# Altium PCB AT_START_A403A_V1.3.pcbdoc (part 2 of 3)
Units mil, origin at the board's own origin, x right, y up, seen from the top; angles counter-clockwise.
Board outline 6370 x 3956 mil, 2 copper layers (Top Layer, Bottom Layer); 182 components, 198 nets, 768 pads, 894 vias.
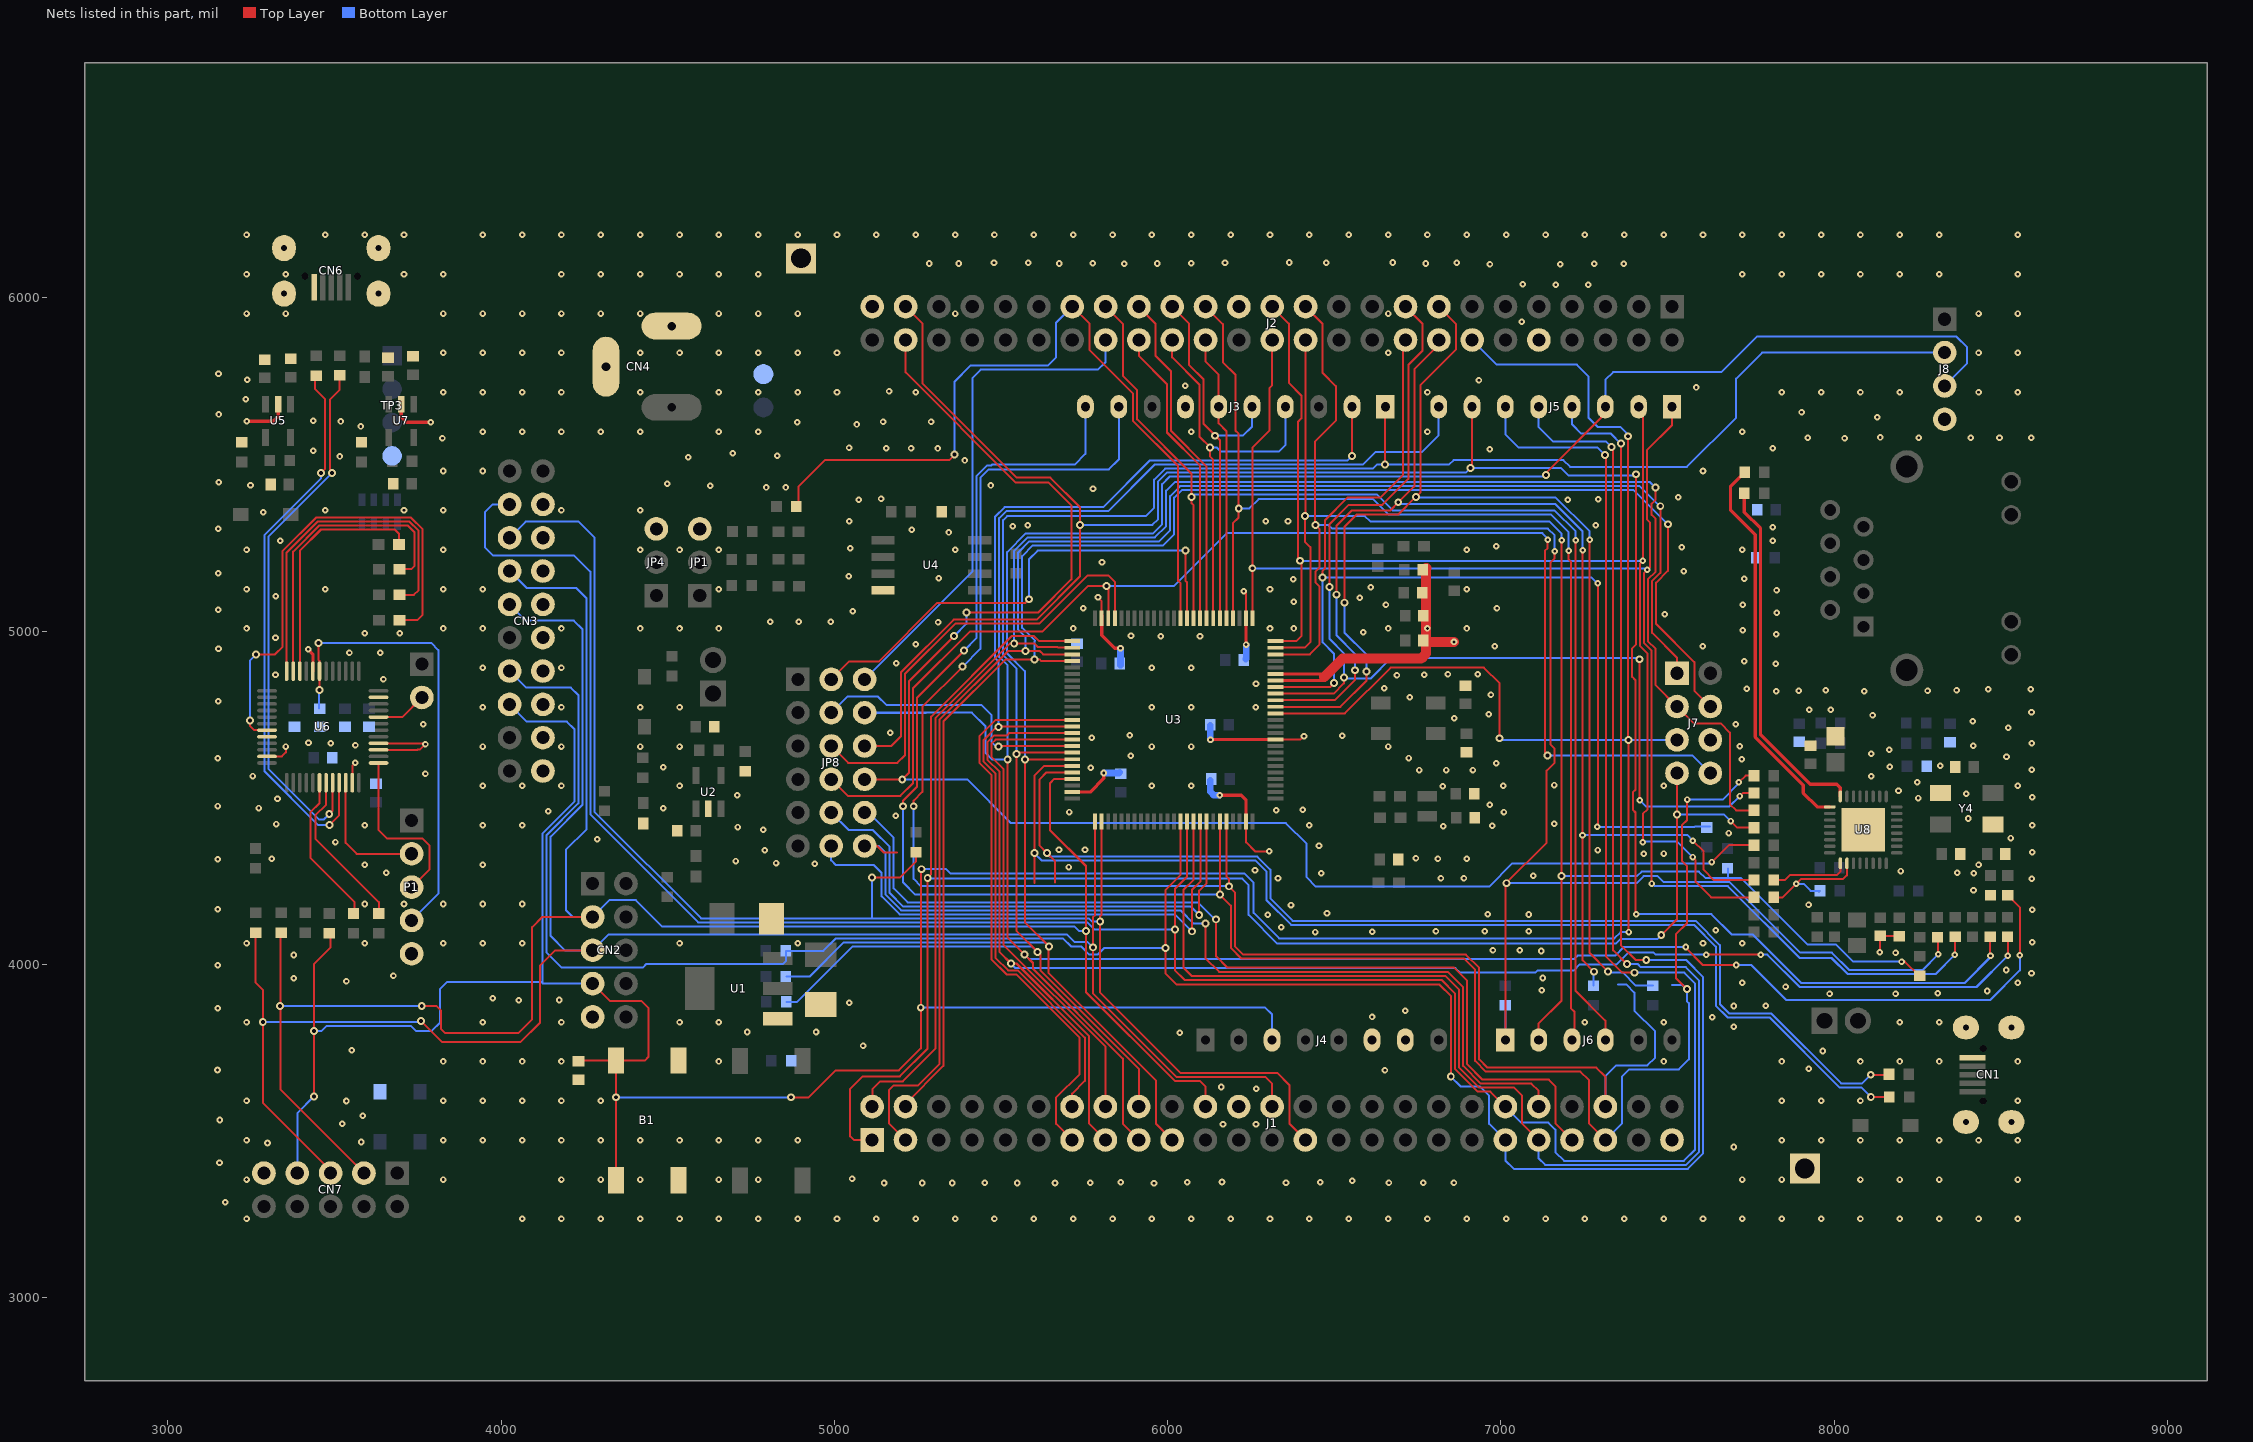
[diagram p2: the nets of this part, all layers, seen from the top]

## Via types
v1: diameter 19.68, hole 7.87, Top Layer to Bottom Layer, 702 vias
v2: diameter 23.62, hole 11.81, Top Layer to Bottom Layer, 166 vias
v3: diameter 35.43, hole 19.68, Top Layer to Bottom Layer, 10 vias
v4: diameter 25.98, hole 12.99, Top Layer to Bottom Layer, 9 vias
v5: diameter 27.56, hole 15.75, Top Layer to Bottom Layer, 5 vias
v6: diameter 43.31, hole 21.65, Top Layer to Bottom Layer, 1 vias
v7: diameter 31.5, hole 19.68, Top Layer to Bottom Layer, 1 vias

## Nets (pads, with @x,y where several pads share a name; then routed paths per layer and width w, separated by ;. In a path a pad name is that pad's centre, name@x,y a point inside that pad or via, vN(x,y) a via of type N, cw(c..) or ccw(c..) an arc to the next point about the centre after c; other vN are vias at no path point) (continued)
GND: B1.2 C1.1 C2.1 C3.1 C4.1 C5.2 C6.2 C7.2 C8.1 C9.1 C10.1 C11.1 C12.1 C14.1 C15.1 C16.1 C17.1 C18.1 C19.1 C22.1 C23.1 C24.1 C25.1 C26.1 C27.1 C29.1 C30.1 C31.1 CB1.1 CB2.1 CB3.1 CB4.1 CB5.1 CB6.1 CB7.1 CB8.2 CB9.2 CB10.1 CB11.1 CB12.1 CB13.1 CB14.1 CN1.5 CN1.6 CN1.7 CN1.8 CN1.9 CN2.9 CN3.4 CN3.6 CN3.8 CN3.10 CN3.12 CN3.14 CN3.16 CN3.18 CN3.20 CN4.2 CN4.3 CN6.5 CN6.6 CN6.7 CN6.8 CN6.9 CN7.9 CT1.2 CT2.2 CT3.1 D4.1 J1.24 J1.49 J2.10 J2.27 J2.49 J3.7 J4.6 J4.7 J7.6 J8.4 JP1.3 JP4.3 LED1.2 P1.5 R14.2 R23.2 R39.2 R49.2 R51.2 R54.1 T1.1 T2.1 TP1.2 TP3.4 U1.1 U2.2 U3.10 U3.19 U3.20 U3.27 U3.49 U3.74 U3.99 U4.4 U5.2 U6.8 U6.20 U6.23 U6.35 U6.39 U6.40 U6.47 U7.2 U8.33 Y4.2 Y4.4 | length 3201.3
  Top Layer w6: U6.23@3297.58,4623.88 3341.88,4623.88 3354.33,4636.33 v1(3354.33,4653.54) ; U6.35@3553.48,4545.14 3553.48,4596.48 v1(3562,4605) ; U6.39@3632.22,4643.56 3748.56,4643.56 3749,4644 3756,4644 v1(3773,4661) 3770.75,4663.25 U6.40@3632.22,4663.25 ; v1(5791,5101) 5802.08,5089.92 U3.49@5802.08,5048.46 ; v1(6228,5120) 6235.15,5112.85 U3.27@6235.15,5048.46 ; U3.99@6235.15,4418.54 6235.15,4365.85 6262,4339 v1(6305,4339) ; U3.10@6333.58,4674.44 6398.44,4674.44 v1(6409,4685) ; v1(8137,4036) 8138,4037 C23.1@8138,4085.44 8194,4085.44 C24.1@8195,4084.44
  Top Layer w10: v1(3237,5630) 3317,5630 3331.23,5644.23 U5.2@3331.23,5680.67 ; v1(3420.8,4945.5) 3435.38,4930.93 U6.8@3435.37,4879.78 ; U7.2@3700.43,5680.6 3700.43,5642.57 3716,5627 v1(3789,5627) ; U3.74@5703.65,4516.96 5767.36,4516.96 5808.58,4558.18 v1(5808.58,4574.18) ; U3.49@5802.08,5048.46 U3.49@5802.08,5038.62 5802.08,4987.68 5841.58,4948.18 v1(5858.58,4948.18) ; v1(6128.58,4673.61) 6129.41,4674.44 U3.10@6323.73,4674.44 U3.10@6333.58,4674.44 ; v1(6156.58,4507.18) 6221.07,4507.18 6235.15,4493.11 U3.99@6235.15,4418.54 ; U3.27@6235.15,5048.46 U3.27@6235.15,5038.62 v1(6235.15,4959.61) v1@6235.58,4959.18 ; U3.19@6323.73,4851.61 6472.7,4851.61 ; U3.20@6323.73,4871.29 6478.89,4871.29 6492.38,4871.29
  Top Layer w30: 6469.29,4861.69 6478.89,4871.29 6524.78,4917.18 6760.58,4917.18 6775.54,4932.14 CB7.1@6775.54,4967.39 ; CB9.2@6775.95,5189.35 6775.54,5188.93 6775.54,5040.76 6774.87,5040.76 6774.87,4968.05 CB7.1@6775.54,4967.39 ; v1@6859.62,4966.98 v1(6859.21,4967.39) CB7.1@6775.54,4967.39
  Bottom Layer w20: v1(5808.58,4574.18) 5853.82,4574.18 CB11.1@5855.78,4576.14 ; CB12.1@5858.58,4897.18 v1(5858.58,4948.18) ; CB10.1@6127.62,4552.39 6127.62,4518.14 6138.58,4507.18 v1(6156.58,4507.18) ; CB14.1@6127.62,4717.39 6127.62,4674.57 v1(6128.58,4673.61) ; CB13.1@6234.58,4916.18 6235.58,4917.18 v1@6235.58,4959.18
  other v1: 3236.22,3236.22 4062.99,3236.22 4181.1,3236.22 4299.21,3236.22 4417.32,3236.22 4535.43,3236.22 4653.54,3236.22 4771.65,3236.22 4889.76,3236.22 5007.87,3236.22 5125.98,3236.22 5244.09,3236.22 5362.2,3236.22 5480.31,3236.22 5598.42,3236.22 5716.53,3236.22 5834.64,3236.22 5952.76,3236.22 6070.87,3236.22 6188.98,3236.22 6307.09,3236.22 6425.2,3236.22 6543.31,3236.22 6661.42,3236.22 6779.53,3236.22 6897.64,3236.22 7015.75,3236.22 7133.86,3236.22 7251.97,3236.22 7370.08,3236.22 7488.19,3236.22 7606.3,3236.22 7724.41,3236.22 7842.52,3236.22 7960.63,3236.22 8078.74,3236.22 8196.85,3236.22 8314.96,3236.22 8433.07,3236.22 8551.18,3236.22 3172,3286 5959,3343 5149,3344 5263.46,3344 5353.92,3344 5549,3344 5662,3344 5451,3345 5768,3345 6355,3345 6664,3345 6767,3345 6859.06,3345 5859,3346 6059,3346 6458,3346 6163,3347 6554,3351 3236.22,3354.33 3826.77,3354.33 4181.1,3354.33 4299.21,3354.33 4417.32,3354.33 4653.54,3354.33 4771.65,3354.33 7724.41,3354.33 7842.52,3354.33 8078.74,3354.33 8196.85,3354.33 8314.96,3354.33 8551.18,3354.33 5053,3357 3155,3405 7698,3452 3299,3464 3580,3467 3236.22,3472.44 3826.77,3472.44 3944.88,3472.44 4062.99,3472.44 4181.1,3472.44 4299.21,3472.44 4417.32,3472.44 4535.43,3472.44 4653.54,3472.44 4771.65,3472.44 4889.76,3472.44 7842.52,3472.44 7960.63,3472.44 8078.74,3472.44 8196.85,3472.44 8314.96,3472.44 8433.07,3472.44 8551.18,3472.44 6166,3520 6265,3520 3523,3522 3156,3533 3585,3546 3536,3590 3236.22,3590.55 3826.77,3590.55 3944.88,3590.55 4062.99,3590.55 4181.1,3590.55 4299.21,3590.55 7842.52,3590.55 7960.63,3590.55 8078.74,3590.55 8551.18,3590.55 6266,3627 6161,3632 6652,3682 3149,3683 7924,3687 3826.77,3708.66 3944.88,3708.66 4062.99,3708.66 4181.1,3708.66 4653.54,3708.66 7488.19,3708.66 7842.52,3708.66 8078.74,3708.66 8196.85,3708.66 8314.96,3708.66 8551.18,3708.66 7966,3740 3552,3742 5086,3756 6036,3795 4738,3797 4945,3797 7698,3813 3236.22,3826.77 3944.88,3826.77 4181.1,3826.77 4535.43,3826.77 4653.54,3826.77 7251.97,3826.77 7488.19,3826.77 8196.85,3826.77 8314.96,3826.77 7634,3841 6613.28,3842.18 6713.28,3860.81 3150,3868 7699,3875 7795,3876 5045,3885 4053,3892 4175,3893 3975,3898 7986,3912 8184,3912 8311,3913 8459,3920 7123,3922 7854,3933 7724.41,3944.88 8551.18,3944.88 3536,3949 3378,3958 7126,3959 3677,3966 8592,3973 8516,3983 3150,3997 3378,4028 8184,4035 7121,4040 6976,4042 7056,4042 3236.22,4062.99 3590.55,4062.99 3826.77,4062.99 3944.88,4062.99 4062.99,4062.99 4535.43,4062.99 4889.76,4062.99 7606.3,4062.99 7724.41,4062.99 8594,4066 6443,4097 6614,4098 6805,4099 6951,4099 7083,4099 7645,4102 6341,4111 6300,4149 7083.55,4149.54 6960.95,4150.91 6478,4153 8594,4164 3150,4165 6370,4178 7923,4179 3590.55,4181.1 3708.66,4181.1 3826.77,4181.1 3944.88,4181.1 4062.99,4181.1 8418,4222 8593,4257 6331,4258 6820,4258 6889,4258 7097,4266 6461,4273 8419,4273 3655,4275 8369,4275 8200,4280 6262,4282 5703,4292 3590.55,4299.21 3944.88,4299.21 8433.07,4299.21 4941,4302 4825,4304 4704,4310 3150,4315 3312,4317 6811,4317 6897,4317 6745,4318 7429,4332 7487.95,4332.5 8594,4336 4791,4342 7290,4343 5674,4344 5752,4344 6454,4356 3503,4367 4288,4375 8530,4379 7684,4394 4786,4404 4710,4412 6827.07,4414.18 6974,4416 3590.55,4417.32 3944.88,4417.32 4062.99,4417.32 6425.2,4417.32 8594,4417 3325,4421 7160,4422 8402.5,4437.61 5184,4446 5705,4457 7009,4457 4141,4459 6326,4462 6405,4464 4486,4468 3273,4469 3150,4475 6966,4479 3329,4497 8252,4499 8594,4501 4709,4507 8396,4512 8192.95,4520.5 6825,4534 3944.88,4535.43 4062.99,4535.43 4181.1,4535.43 4535.43,4535.43 5952.76,4535.43 6070.87,4535.43 7488.19,4535.43 8551.18,4535.43 7007,4536 7160,4538 8249,4546 8111,4564 3255,4565 3773,4571.78 6755,4583 6836,4583 6916,4583 8593,4584 5769,4590 4486,4591 8167,4593 8318,4596 6986,4603 7723,4615 3150,4618 6723,4619 8517,4623 5889,4626 8111,4632 8165,4644 3944.88,4653.54 4181.1,4653.54 4417.32,4653.54 4535.43,4653.54 5952.76,4653.54 6070.87,4653.54 6661.42,4653.54 7717,4655 8417,4656 3563,4657 8593,4663 3489,4664 3422,4665 5772,4680 6524,4686 5886,4687 5168,4695 8522,4710 3766,4720 7704,4720 8416,4730 6860,4739 8115,4748 6963,4751 8592,4757 7925,4764 7990,4764 6264,4771 3944.88,4771.65 4181.1,4771.65 4417.32,4771.65 4535.43,4771.65 5952.76,4771.65 6070.87,4771.65 3151,4789 6726,4802 6970,4809 7826,4820 8090,4820 7894,4821 8280,4821 7975,4822 8367,4823 8462,4826 8590,4826 7738,4827 6650,4828 6265,4842 3647,4855 6688,4868 3323,4869 6770,4869 6930,4870 6841,4871 3944.88,4889.76 4181.1,4889.76 5952.76,4889.76 6070.87,4889.76 7825,4902 5186,4904 7730,4910 3545,4935 3637,4935 3152,4947 7605,4954 6981,4955 5244,4961 3323,4980 6097,4984 5979,4985 5890,4986 7826,4990 3591,4993 3696,4993 6587,4996 7726,5002 3236.22,5007.87 3826.77,5007.87 3944.88,5007.87 4181.1,5007.87 4417.32,5007.87 4535.43,5007.87 4653.54,5007.87 5716.53,5007.87 6307.09,5007.87 6378.37,5007.87 6661.42,5007.87 6779.53,5007.87 6897.64,5007.87 5311,5026 4808,5028 4893,5028 4989,5028 7492,5051 7828,5055 5055,5059 3151,5064 5747,5068 6988,5068 6655,5079 7726,5079 6378,5088 6576,5100 3324,5104 7827,5123 3236.22,5125.98 3472.44,5125.98 3826.77,5125.98 3944.88,5125.98 4653.54,5125.98 6307.09,5125.98 6897.64,5125.98 6609.42,5130.97 6377,5156 7730,5157 5313,5159 5043,5165 3151,5174 7548,5179 5803,5207 3236.22,5244.09 3826.77,5244.09 4417.32,5244.09 4535.43,5244.09 4653.54,5244.09 5362.2,5244.09 6897.64,5244.09 7724.41,5244.09 5048,5248 7543,5252 6986,5254 3337,5271 7816,5271 5343.32,5295.92 5232.27,5303.8 3151,5307 7816,5311 5535,5314 5580,5318 7285,5318 6294,5329 6361,5329 5045,5330 3286,5356 3472.44,5362.2 3708.66,5362.2 3826.77,5362.2 4181.1,5362.2 4417.32,5362.2 5073,5394 7200,5394 7292,5396 5140,5397 7532,5402 5776,5427 4795,5431 4854,5431 4627,5436 5469,5437 3248,5438 4498,5442 3153,5447 3826.77,5480.31 3944.88,5480.31 7606.3,5480.31 5391,5512 4562,5522 3516,5524 4829,5526 4695,5534 3436,5541 6966,5546 5310,5548 5156,5549 5230,5549 7816,5549 5044,5550 3824,5579 8031,5579 7921,5580 8253.45,5580 8410,5580 8496.01,5580 8591,5580 8138,5581 3944.88,5598.42 4062.99,5598.42 4181.1,5598.42 4299.21,5598.42 4417.32,5598.42 4653.54,5598.42 4771.65,5598.42 6070.87,5598.42 6779.53,5598.42 7724.41,5598.42 3579,5614 5067,5620 4889,5627 5146,5628 5290,5628 3519,5629 3436.41,5630.67 8129,5642 3153,5650 7902,5657 3234,5696 3826.77,5716.53 3944.88,5716.53 4062.99,5716.53 4181.1,5716.53 4417.32,5716.53 4653.54,5716.53 4771.65,5716.53 4889.76,5716.53 5007.87,5716.53 5244.09,5716.53 6779.53,5716.53 7842.52,5716.53 7960.63,5716.53 8078.74,5716.53 8196.85,5716.53 8433.07,5716.53 8551.18,5716.53 5164,5720 7586,5731 6053.28,5736.15 6934,5753 3238,5754 3152,5772 3826.77,5834.64 3944.88,5834.64 4062.99,5834.64 4181.1,5834.64 4417.32,5834.64 4535.43,5834.64 4653.54,5834.64 4771.65,5834.64 4889.76,5834.64 5007.87,5834.64 6661.42,5834.64 8433.07,5834.64 8551.18,5834.64 7062,5928 3236.22,5952.76 3354.33,5952.76 3826.77,5952.76 3944.88,5952.76 4062.99,5952.76 4181.1,5952.76 4299.21,5952.76 4417.32,5952.76 4653.54,5952.76 4771.65,5952.76 4889.76,5952.76 5362.2,5952.76 6661.42,5952.76 8433.07,5952.76 8551.18,5952.76 7164,6039 7261.86,6039 7066,6041 3236.22,6070.87 3354.33,6070.87 3708.66,6070.87 3826.77,6070.87 4181.1,6070.87 4299.21,6070.87 4417.32,6070.87 4535.43,6070.87 4653.54,6070.87 4771.65,6070.87 7724.41,6070.87 7842.52,6070.87 7960.63,6070.87 8078.74,6070.87 8196.85,6070.87 8314.96,6070.87 8551.18,6070.87 6967,6101 7177.76,6101 5870,6102 7280,6102 7369,6102 5285,6103 5373,6103 5675,6103 5969,6103 6774,6103 5775,6104 6071,6104 5479,6105 5582,6105 6172,6105 6476,6105 6867,6105 6365,6106 6675,6106 3236.22,6188.98 3472.44,6188.98 3590.55,6188.98 3708.66,6188.98 3944.88,6188.98 4062.99,6188.98 4181.1,6188.98 4299.21,6188.98 4417.32,6188.98 4535.43,6188.98 4653.54,6188.98 4771.65,6188.98 4889.76,6188.98 5007.87,6188.98 5125.98,6188.98 5244.09,6188.98 5362.2,6188.98 5480.31,6188.98 5598.42,6188.98 5716.53,6188.98 5834.64,6188.98 5952.76,6188.98 6070.87,6188.98 6188.98,6188.98 6307.09,6188.98 6425.2,6188.98 6543.31,6188.98 6661.42,6188.98 6779.53,6188.98 6897.64,6188.98 7015.75,6188.98 7133.86,6188.98 7251.97,6188.98 7370.08,6188.98 7488.19,6188.98 7606.3,6188.98 7724.41,6188.98 7842.52,6188.98 7960.63,6188.98 8078.74,6188.98 8196.85,6188.98 8314.96,6188.98 8551.18,6188.98
JDI: CN3.5 J1.27 R36.1 U3.77 | length 4453.1
  Top Layer w6: v2(5112.58,4260.5) 5195.53,4260.5 5245.03,4310 R36.1@5245.03,4335.03 ; U3.77@5802.08,4428.38 5802.08,4149.18 5797.58,4144.68 v2(5797.58,4128.18) 5797.58,3915.27 6038.32,3674.53 6328.23,3674.53 6365.58,3637.18 6365.58,3521.59 J1.27@6413.71,3473.46
  Bottom Layer w6: CN3.5@4025.58,5280.18 4073.58,5328.18 4232.58,5328.18 4279.58,5281.18 4279.58,4458.56 4599.95,4138.18 5112.95,4138.18 ; v2(5112.58,4260.5) 5112.58,4138.56 5112.95,4138.18 ; v2(5797.58,4128.18) 5773.67,4128.18 5763.67,4138.18 5112.95,4138.18
JDO: CN3.13 J1.39 J5.4 R4.1 U3.89 | length 8128.1
  Top Layer w6: U3.89@6038.3,4428.38 6038.3,4267.91 5993,4222.61 v2(5993,4049) 5993,3972.82 6026.63,3939.18 6815.58,3939.18 6850.58,3904.18 6850.58,3664.18 v2(6849.58,3663.18) ; v2(7359.95,5562.5) 7360.95,5561.5 7360.95,4056.05 7404,4013 v2(7436,4013)
  Bottom Layer w6: CN3.13@4025.58,4880.18 4075.58,4830.18 4209.58,4830.18 4231.58,4808.18 4231.58,4483.15 4136.58,4388.15 4136.58,4035.18 4180.58,3991.18 4425.95,3991.18 4436.27,4001.5 4846.45,4001.5 4855.42,4010.47 4855.42,4040.51 4967.14,4040.51 5004.81,4078.18 5685.82,4078.18 5710.37,4053.63 5740.37,4053.63 5765,4029 5789.4,4029 5809.4,4049 v2(5993,4049) ; v2(6849.58,3663.18) 6878.58,3634.18 6936.58,3634.18 6964.58,3606.18 6964.58,3521.74 J1.39@7013.28,3473.03 7013.28,3411.48 7038.58,3386.18 7560.55,3386.18 7606.95,3432.59 7606.95,3961.5 7555.45,4013 v2(7436,4013) ; J5.4@7213.28,5673.03 7213.28,5620.17 7241.21,5592.24 7330.21,5592.24 v2(7359.95,5562.5)
JTCK: CN2.5 CN3.9 CN7.5 J1.26 R41.2 U3.76 | length 6172.9
  Top Layer w6: R41.2@3263.43,4095.78 3263.43,3945.29 3284.95,3923.77 v2(3284.95,3827.5) 3284.95,3584.26 3488.43,3380.78 CN7.5@3488.43,3373.78 ; v2(3759.95,3829.5) 3822.95,3766.5 4057.92,3766.5 4116.95,3825.53 4116.95,3996.78 4162.35,4042.18 CN2.5@4274.58,4042.18 ; U3.76@5782.39,4428.38 5782.39,4148 5775.58,4141.18 5775.58,4109.31 5775.76,4109.12 5775.76,4051.37 v2(5775.58,4051.18) 5775.58,3913.22 6026.27,3662.53 6292.58,3662.53 6313.71,3641.4 J1.26@6313.71,3573.46
  Bottom Layer w6: v2(3284.95,3827.5) 3757.95,3827.5 v2(3759.95,3829.5) ; CN3.9@4025.58,5080.18 4074.58,5031.18 4218.58,5031.18 4243.58,5006.18 4243.58,4478.18 4148.58,4383.18 4148.58,4085.18 4191.58,4042.18 CN2.5@4274.58,4042.18 4322.58,4090.18 5697.82,4090.18 5721,4067 5759.76,4067 v2(5775.58,4051.18)
JTMS: CN2.3 CN3.7 CN7.3 J1.22 R44.2 U3.72 | length 6267.7
  Top Layer w6: R44.2@3337.43,4095.78 3337.43,3625.78 3588.43,3374.78 CN7.3@3588.43,3373.78 ; v2(3761.95,3875.5) 3804.95,3875.5 3820.13,3860.32 3820.13,3805.32 3831.95,3793.5 4050.95,3793.5 4092.95,3835.5 4092.95,4111.5 4123.64,4142.18 CN2.3@4274.58,4142.18 ; U3.72@5713.5,4556.33 5660.33,4556.33 5647,4543 5647,4403 5754.95,4295.05 v2(5754.95,4100.5) 5754.76,4100.31 5754.76,3917.06 6021.3,3650.53 6096.23,3650.53 6113.71,3633.05 J1.22@6113.71,3573.46
  Bottom Layer w6: v2(3336.95,3875.5) v2(3761.95,3875.5) ; CN3.7@4025.58,5180.18 4076.58,5129.18 4225.58,5129.18 4255.58,5099.18 4255.58,4404.5 4194.58,4343.5 4194.58,4163.18 4215.58,4142.18 CN2.3@4274.58,4142.18 4324.89,4192.5 4404.26,4192.5 4482.58,4114.18 5719.82,4114.18 5733.5,4100.5 v2(5754.95,4100.5)
JTRST: CN3.3 J1.40 J5.6 U3.90 | length 8319.2
  Top Layer w6: U3.90@6057.99,4428.38 6057.99,4262.59 6021.58,4226.18 v2(6021.58,4104.18) 6021.58,3982.18 6050.58,3953.18 6821.58,3953.18 6862.58,3912.18 6862.58,3685.42 6929.81,3618.18 6968.13,3618.18 J1.40@7013.28,3573.03 ; v2(7311.95,5528.5) 7314.95,5525.5 7314.95,4024.05 7364,3975 v2(7401,3975)
  Bottom Layer w6: CN3.3@4025.58,5380.18 3975.58,5380.18 3951.58,5356.18 3951.58,5251.18 3975.58,5227.18 4218.58,5227.18 4267.58,5178.18 4267.58,4449.88 4591.27,4126.18 5758.7,4126.18 5780.7,4104.18 v2(6021.58,4104.18) ; J1.40@7013.28,3573.03 7061.13,3525.18 7142.58,3525.18 7163.58,3504.18 7163.58,3436.18 7189.58,3410.18 7548.58,3410.18 7582.95,3444.56 7582.95,3942.05 7550.04,3974.96 v2(7401,3975) ; J5.6@7013.28,5673.03 7013.28,5590.48 7052.58,5551.18 7289.27,5551.18 v2(7311.95,5528.5)
LD1: LD1.2 U6.10 | length 723.1
  Top Layer w6: U6.10@3396,4879.78 3396.01,5241.19 3459.6,5304.78 3681.43,5304.78 3693.43,5292.78 LD1.2@3693.43,5259.78
LD2: LD2.2 U6.11 | length 914.2
  Top Layer w6: U6.11@3376.32,4879.78 3376.32,5238.48 3454.63,5316.78 3719.43,5316.78 3740.43,5295.78 3740.43,5195.78 3730.34,5185.69 LD2.2@3694.39,5185.69
LD3: LD3.2 U6.12 | length 1043.7
  Top Layer w6: U6.12@3356.63,4879.78 3356.64,5235.76 3449.66,5328.78 3724.4,5328.78 3752.43,5300.75 3752.43,5122.78 3738.43,5108.78 LD3.2@3694.43,5108.78
LD4: LD4.2 U6.19 | length 1465.2
  Top Layer w6: v2(3246,4732) 3246,4716 3259.38,4702.62 U6.19@3297.58,4702.62 ; v2(3264.95,4929.78) 3321.43,4929.78 3344.64,4952.99 3344.64,5240.73 3444.69,5340.78 3729.37,5340.78 3764.43,5305.73 3764.43,5048.78 3748.43,5032.78 LD4.2@3694.39,5032.78
  Bottom Layer w6: v2(3246,4732) 3247,4733 3247,4911.83 v2(3264.95,4929.78)
LED_G: R60.1 U8.8 | length 1076.5
  Top Layer w10: R60.1@7730.34,5414 7730.34,5356.66 7779,5308 7779,4688.63 7927.63,4540 8008,4540 8018.31,4529.69 U8.8@8018.31,4503.89
LED_Y: R61.1 U8.9 | length 1167.9
  Top Layer w10: R61.1@7731.34,5477 7689,5434.66 7689,5363 7763,5289 7763,4682 7907,4538 7907,4514 7948.6,4472.4 U8.9@7986.81,4472.4
M-ATLK_RX: R48.1 U6.31 | length 483.9
  Top Layer w6: U6.31@3474.74,4545.14 3474.75,4479.1 3442.43,4446.78 3442.43,4377.44 3633.43,4186.44 R48.1@3633.43,4153.78
M-ATLK_TX: R47.1 U6.30 | length 457.3
  Top Layer w6: U6.30@3455.06,4545.14 3455.06,4483.41 3427.69,4456.04 3427.69,4319.52 3559.43,4187.78 R47.1@3559.43,4153.78
M-BOOT0: J9.2 U6.44 | length 154.6
  Top Layer w6: U6.44@3632.22,4741.99 3703.64,4741.99 J9.2@3762.43,4800.78
M-NRST: C22.2 P1.4 U6.7 | length 1411.3
  Top Layer w6: v2(3451.95,4964.5) 3451.95,4913.77 3455.06,4910.66 U6.7@3455.06,4879.78 3455.06,4823.22 v2(3454.63,4822.78)
  Bottom Layer w6: v2(3451.95,4964.5) 3790.39,4964.5 3812.02,4942.87 3812.02,4212.37 P1.4@3731.43,4131.78 ; C22.2@3453.94,4768.12 v2@3453.94,4822.78
M-SWCLK: P1.3 U6.37 | length 520.5
  Top Layer w6: U6.37@3632.22,4604.19 3632.23,4402.69 3657.13,4377.78 3763.43,4377.78 3785.43,4355.78 3785.43,4285.78 P1.3@3731.43,4231.78
M-SWDIO: P1.2 U6.34 | length 391.9
  Top Layer w6: U6.34@3533.8,4545.14 3533.8,4364.41 3566.43,4331.78 P1.2@3731.43,4331.78
M-USB_DM: R38.1 U6.32 | length 1621.4
  Top Layer w6: v2(3484.43,4450.78) 3494.43,4460.78 U6.32@3494.43,4545.14 ; v2(3493.01,5474.78) 3486,5481.8 3486,5694.35 3515.43,5723.78 R38.1@3515.43,5762.63
  Bottom Layer w6: v2(3484.43,4450.78) 3468.65,4435 3452.93,4435 3301.43,4586.5 3301.43,5283.2 v2(3493.01,5474.78)
M-USB_DP: R37.1 U6.33 | length 1671.8
  Top Layer w6: R37.1@3441.43,5761.67 3441.43,5726.78 3472,5696.22 3472,5486.77 v2(3460.01,5474.78) ; v2(3485,4418) 3514.12,4447.12 U6.33@3514.11,4545.14
  Bottom Layer w6: v2(3460.01,5474.78) 3460.01,5458.75 3289.43,5288.18 3289.43,4580.11 3451.54,4418 v2(3485,4418)
MDC: R77.1 U8.17 | length 235
  Top Layer w6: R77.1@7818.66,4253 7852,4253 7867.5,4268.5 8008.64,4268.5 8018.31,4278.17 U8.17@8018.31,4303.1
MDIO: R55.2 R78.1 U8.18 | length 366.2
  Top Layer w6: R78.1@7818.66,4201 7845.45,4201 v1(7885.95,4241.5) 7899.95,4255.5 8026.12,4255.5 8037.99,4267.37 U8.18@8037.99,4303.1
  Bottom Layer w6: v1(7885.95,4241.5) 7907.92,4241.5 7928.92,4220.5 7956.64,4220.5 R55.2@7953.64,4217.5
NRST: B1.1 CB1.2 CN2.7 CN3.15 CN7.7 J2.14 J4.3 J7.5 R46.2 U3.14 | length 12191.3
  Top Layer w6: v2(3438.43,3603.5) v2(3438.43,3800.5) 3438.43,4000.78 3488.43,4050.78 3488.43,4090.78 R46.2@3485.43,4093.78 ; CB1.2@4233.58,3711.18 B1.1@4344.58,3711.18 ; CN2.7@4278.95,3942.18 CN2.7@4274.58,3942.18 4326.26,3890.5 4420.95,3890.5 4442.95,3868.5 4442.95,3723.5 4430.64,3711.18 B1.1@4344.58,3711.18 ; B1.1@4344.58,3352.18 v2(4344.58,3601.18) B1.1@4344.58,3711.18 ; v2(4869.95,3601.18) 4922.64,3601.18 5003.64,3682.18 5193.33,3682.18 5259.14,3747.99 v2(5259.14,3869.99) 5259.14,4283.69 v2(5260.95,4285.5) ; U3.14@6323.73,4753.18 6531.64,4753.18 6668.95,4890.5 6948.95,4890.5 6995.95,4843.5 v2(6995.95,4678.5) ; v2@7381.76,4678.5 v2(7381.76,5584.5) ; v1(7383,4097) v2(7382.95,4673.61)
  Bottom Layer w6: CN7.7@3388.43,3373.78 3388.43,3553.5 v2(3438.43,3603.5) ; v2(3438.43,3800.5) 3461.57,3800.5 3476.57,3815.5 3728.95,3815.5 3743.95,3800.5 3791.92,3800.5 3816.95,3825.53 3816.95,3926.5 3837.95,3947.5 4124.58,3947.5 4124.58,4393.12 4219.58,4488.12 4219.58,4706.18 4197.58,4728.18 4077.58,4728.18 CN3.15@4025.58,4780.18 ; 4124.58,3942.18 CN2.7@4274.58,3942.18 ; v2(4344.58,3601.18) v2(4869.95,3601.18) ; v2(5259.14,3869.99) 6292.76,3869.99 6313.28,3849.48 J4.3@6313.28,3773.03 ; v2(5260.95,4285.5) 5335.35,4285.5 5348.85,4272 6231,4272 6258,4245 6258,4154.45 6334.3,4078.16 7340.16,4078.16 7359,4097 v1(7383,4097) ; J2.14@6913.28,5873.03 6987.13,5799.18 7227.5,5799.18 7262.95,5763.73 7262.95,5639.38 7289.77,5612.57 7357.89,5612.57 7381.76,5588.69 v2(7381.76,5584.5) ; v2(6995.95,4678.5) 6995.95,4677.89 7000.23,4673.61 v2(7382.95,4673.61) J7.5@7528.28,4673.61
PA0: J2.23 J6.1 R19.1 R84.1 U3.23 | length 5149.7
  Top Layer w6: U3.23@6323.73,4930.35 6426.35,4930.35 6455,4959 6455,5134.46 6443.95,5145.51 6443.95,5179.2 6456,5191.25 6456,5306.14 v2(6443.95,5318.18) 6441.58,5320.56 6441.58,5568.18 6504.58,5631.18 6504.58,5735.18 6464.58,5775.18 6464.58,5921.74 J2.23@6413.28,5973.03 ; J6.1@7013.28,3773.03 7013.28,4241.83 7136.95,4365.49 7136.95,4580.93 7161,4604.98 7161,4647 7148,4660 7148,5205.01 7161,5218.01 v1(7161,5239) ; R84.1@8310,4081.34 8312,4079.34 v1(8312,4030)
  Bottom Layer w6: v2(6443.95,5318.18) 6482.34,5318.18 6493.2,5307.32 7140.63,5307.32 7160.95,5287 v1(7161,5239) ; J6.1@7013.28,3773.03 7013.28,3874.59 7013.58,3874.88 R19.1@7013.58,3878.18 ; v2(7016.95,4243.5) 7406.95,4243.5 7427.95,4264.5 7470.5,4264.5 7488.5,4246.5 7686.03,4246.5 7897.66,4034.87 7993.08,4034.87 8044.94,3983 8265,3983 v1(8312,4030)
PA1: J2.24 J6.2 R68.1 R69.2 U3.24 | length 4601.9
  Top Layer w6: U3.24@6323.73,4950.03 6411.43,4950.03 6427.95,4966.56 6427.95,5251.78 6411.95,5267.78 v2(6411.95,5345.18) 6413.28,5346.51 J2.24@6413.28,5873.03 ; J6.2@7113.28,3773.03 7113.28,3822.83 7181.95,3891.5 v2(7181.95,4265.5) v1(7181.95,5272.5) ; v1(8202,4008) 8212,4008 8254.66,3965.34 R69.2@8257,3965.34
  Bottom Layer w6: v2(6411.95,5345.18) 6591.82,5345.18 6608,5329 7145,5329 7181.95,5292.05 v1(7181.95,5272.5) ; v2(7181.95,4265.5) 7408.95,4265.5 7421.95,4278.5 7593.95,4278.5 7613.95,4258.5 7720.5,4258.5 7920,4059 8006,4059 8057,4008 v1(8202,4008) ; 7680.88,4259.42 R68.1@7680.88,4287.03
PA2: J2.25 J5.2 R78.2 U3.25 | length 3924.3
  Top Layer w6: J2.25@6313.28,5973.03 6363.58,5922.74 6363.58,5744.59 6401.28,5706.89 6401.28,5638.3 6391.14,5628.16 6391.14,5216.86 v2(6397,5211) 6401,5207 6401,4985 6385.72,4969.72 U3.25@6323.73,4969.72 ; J5.2@7413.28,5673.03 7425.95,5660.36 v1(7425.95,5211.5) 7416.95,5202.5 7416.95,4955.5 7439.95,4932.5 7439.95,4465.5 7425.95,4451.5 v1(7425.95,4366.5) ; v1(7575,4322) 7584,4313 7584,4247.6 7630.6,4201 R78.2@7759.34,4201
  Bottom Layer w6: v2(6397,5211) 7425.45,5211 v1(7425.95,5211.5) ; v1(7425.95,4366.5) 7424.95,4366.5 7422.95,4368.5 7528.5,4368.5 v1(7575,4322)
PA3: J2.26 J5.1 R85.1 U3.26 | length 4618
  Top Layer w6: U3.26@6254.84,5048.46 6254.84,5551.44 6304.95,5601.56 6304.95,5729.17 6313.28,5737.5 J2.26@6313.28,5873.03 ; v1(7452.95,4242.5) 7451.95,4243.5 7451.95,4941.5 7428.95,4964.5 7428.95,5173.5 v1(7438.95,5183.5) 7446.95,5191.5 7446.95,5326.5 7437.95,5335.5 7437.95,5542.5 7513.28,5617.82 J5.1@7513.28,5673.03 ; v1(8362,4029) 8362,4081.34 R85.1@8363,4082.34
  Bottom Layer w6: v2(6253.95,5188.5) 7433.95,5188.5 v1(7438.95,5183.5) ; v1(7452.95,4242.5) 7460.95,4234.5 7681.06,4234.5 7896.47,4019.09 7991.88,4019.09 8039.97,3971 8304,3971 v1(8362,4029)
PA4: J2.29 J6.3 U3.29 | length 3560
  Top Layer w6: J2.29@6113.28,5973.03 6165.58,5920.74 6165.58,5807.18 6202.95,5769.81 6202.95,5601.82 6213.28,5591.5 v2(6213.28,5368.18) 6213.28,5340.89 6195.78,5323.39 U3.29@6195.78,5038.62 ; v1(7203,5241) 7203,5215.13 7210,5208.13 7210,3868 7221,3857 7221,3780.75 J6.3@7213.28,3773.03
  Bottom Layer w6: v2(6213.28,5368.18) 6245.45,5368.18 6273.27,5396 6616.65,5396 6662.15,5350.5 7149.5,5350.5 7203,5297 v1(7203,5241)
PA5: J2.30 J3.6 U3.30 | length 860.4
  Top Layer w6: J2.30@6113.28,5873.03 6113.28,5809.48 6153.28,5769.48 J3.6@6153.28,5673.03 6153.28,5623.18 6176.1,5600.37 U3.30@6176.1,5038.62
PA6: J2.31 J3.5 U3.31 | length 1175
  Top Layer w6: J2.31@6013.28,5973.03 6064.58,5921.74 6064.58,5798.18 6107.58,5755.18 6107.58,5622.1 6156.41,5573.26 U3.31@6156.41,5038.62
  Bottom Layer w6: v2(6142.58,5586.18) 6225.58,5586.18 6253.28,5613.89 J3.5@6253.28,5673.03
PA7: J2.32 J3.4 U3.32 | length 1239.9
  Top Layer w6: J2.32@6013.28,5873.03 6013.28,5821.48 6095.58,5739.18 6095.58,5583.18 v2(6127.58,5551.18) 6127.58,5523.18 6136.73,5514.03 U3.32@6136.73,5038.62
  Bottom Layer w6: v2(6127.58,5551.18) 6146.58,5551.18 6159.58,5538.18 6333.58,5538.18 6353.28,5557.89 J3.4@6353.28,5673.03
PA8: JP8.5 U3.67 | length 852.6
  Top Layer w6: v2(5492.95,4653.5) 5494.21,4654.76 U3.67@5713.5,4654.76
  Bottom Layer w6: JP8.5@4990.58,4755.18 5038.89,4803.5 5130.95,4803.5 5155.95,4778.5 5440.92,4778.5 5470.95,4748.47 5470.95,4668.19 5485.65,4653.5 v2(5492.95,4653.5)
PA8_E: J1.17 J5.8 JP8.6 R64.2 | length 7613
  Top Layer w6: v2@5520.03,4609.64 5520.03,4079.97 v2(5570,4030) 5596,4004 5596,3986.88 5865.58,3717.3 5865.58,3521.59 J1.17@5913.71,3473.46 ; v1(7554,4052) 7554,4050 7606,3998 v1(7706,3998) ; R64.2@8521,4207.34 8557,4171.34 v1(8557,4027)
  Bottom Layer w6: v2(5570,4030) 5583.81,4016.19 7220.19,4016.19 7230,4026 7343,4026 7369,4052 v1(7554,4052) ; J5.8@6813.28,5673.03 6813.28,5587.59 6762.69,5537 6623,5537 6585.18,5499.18 5960.58,5499.18 5821.58,5360.18 5515.95,5360.18 5494.58,5338.81 5494.58,4922.83 5520.03,4897.37 v2(5520.03,4614.5) 5473.63,4614.5 5453.46,4634.67 5453.46,4713.91 5412.19,4755.18 5276.04,4755.18 ; v1(7706,3998) 7751,3998 7856,3893 8468,3893 8557,3982 v1(8557,4027) ; 5276.04,4755.18 5275.54,4754.69 5091.07,4754.69 JP8.6@5090.58,4755.18 5276.04,4755.18
PA9: J1.18 J3.1 J8.2 R10.1 U3.68 | length 6268.2
  Top Layer w6: U3.68@5713.5,4635.07 5713.5,4635.31 5549.76,4635.31 v2(5545.95,4631.5) 5545.95,4101.05 v2(5610,4037) 5619,4028 5619,3980.85 5913.71,3686.14 J1.18@5913.71,3573.46 ; v2(6652.58,5500.18) 6652.58,5671.74 6653.58,5672.74 J3.1@6653.28,5673.03
  Bottom Layer w6: R10.1@4856.89,3887.52 4887.98,3887.52 5054.64,4054.18 5592.82,4054.18 v2(5610,4037) ; v2(5545.95,4631.5) 5545.95,4888.42 5506.58,4927.8 5506.58,5333.18 5518.58,5345.18 5934.58,5345.18 5959.58,5370.18 5959.58,5454.15 5992.61,5487.18 6615.58,5487.18 6628.58,5500.18 v2(6652.58,5500.18) 6844.87,5500.18 6857.87,5513.18 7187.27,5513.18 7207.95,5492.5 7557.95,5492.5 7705.95,5640.5 7705.95,5757.5 7783.95,5835.5 J8.2@8331.46,5835.5
PA10: J1.19 J5.3 J8.3 R9.1 U3.69 | length 6388.2
  Top Layer w6: U3.69@5713.5,4615.39 5572.47,4615.39 v2(5571.58,4614.5) 5571.58,4126.42 v2(5644,4054) 5642,4052 5642,3974.82 5964.58,3652.24 5964.58,3522.59 J1.19@6013.71,3473.46 ; v2(7135.58,5468.15) 7135.58,5475.12 7313.28,5652.82 J5.3@7313.28,5673.03
  Bottom Layer w6: R9.1@4855.89,3963.52 4926.03,3963.52 5028.69,4066.18 5631.82,4066.18 v2(5644,4054) ; v2(5571.58,4614.5) 5571.58,4879.77 5518.58,4932.77 5518.58,5237.15 5574.61,5293.18 5956.58,5293.18 5983.58,5320.18 5983.58,5441.18 6005.58,5463.18 7130.61,5463.18 v2(7135.58,5468.15) v2@7135.94,5468.51 ; J5.3@7313.28,5673.03 7313.28,5753.51 7336.95,5777.18 7661.64,5777.18 7767.95,5883.5 8366.95,5883.5 8398.95,5851.5 8398.95,5803 J8.3@8331.46,5735.5
PA11: R22.1 U3.70 | length 3470
  Top Layer w6: v2(5600,4334) 5599.95,4565.75 5629.91,4595.7 U3.70@5713.5,4595.7 ; v2(5600,4334) 5600,4284.65 5601,4283.65 5601,4244.12 ; v2(8109.77,3602.5) R22.1@8164.95,3602.5
  Bottom Layer w6: v2(5600,4334) 5623,4311 6264.03,4311 6296,4279.03 6296,4193.03 6370.33,4118.7 7579.3,4118.7 7645,4053 7645,3876 7680.49,3840.51 7806.49,3840.51 8017,3630 8082.27,3630 v2(8109.77,3602.5)
PA12: R20.1 U3.71 | length 3415
  Top Layer w6: 5661.74,4245.38 5661.74,4310.26 v2(5638,4334) 5615.66,4356.34 5615.66,4555.2 5636.47,4576.02 U3.71@5713.5,4576.02 ; v2(8109.59,3668.76) R20.1@8164.95,3668.76
  Bottom Layer w6: v2(5638,4334) 5638,4331 5646,4323 6269,4323 6308,4284 6308,4198 6375.3,4130.7 7584.27,4130.7 7657,4057.97 7657,3880.97 7685.46,3852.51 7811.46,3852.51 8020.97,3643 8083.83,3643 v2(8109.59,3668.76)
PB0: J2.35 J6.4 U3.35 | length 3808.9
  Top Layer w6: J2.35@5813.71,5973.46 5866.58,5920.59 5866.58,5765.18 5908.58,5723.18 5908.58,5635.18 6071.58,5472.18 v2(6071.58,5402.18) 6071.58,5383.28 6077.67,5377.18 U3.35@6077.67,5038.62 ; v1(7223.95,5272.5) 7223.76,5272.31 7223.76,3920.69 7313.28,3831.17 J6.4@7313.28,3773.03
  Bottom Layer w6: v2(6071.58,5402.18) 6079.39,5410 6627.45,5410 6674.95,5362.5 7160.5,5362.5 7223.95,5299.05 v1(7223.95,5272.5)
PB1: JP8.2 U3.36 | length 1497.8
  Top Layer w6: JP8.2@4990.58,4855.18 5043.58,4908.18 5132.49,4908.18 5308.8,5084.5 5572.95,5084.5 v2(5583.95,5095.5) ; v2(6053.28,5241.5) 6053.28,5151.48 6057.99,5146.77 U3.36@6057.99,5038.62
  Bottom Layer w6: v2(5583.95,5095.5) 5583.95,5215.5 5609.95,5241.5 v2(6053.28,5241.5)
PB1_E: J2.36 JP8.3 | length 1524
  Bottom Layer w6: JP8.3@5090.58,4855.18 5413.71,5178.31 5413.71,5759.25 5438.64,5784.18 5790.58,5784.18 5813.71,5807.31 J2.36@5813.71,5873.46
PB2: J2.37 R25.2 U3.37 | length 2364.7
  Top Layer w6: R25.2@4891.91,5373.02 4891.91,5433.46 4971.45,5513 5344.08,5513 v2(5360.58,5529.5) ; J2.37@5713.71,5973.46 5765.58,5921.59 5765.58,5843.28 5896.58,5712.28 5896.58,5630.21 6030.95,5495.84 6030.95,5151.81 6038.3,5144.46 U3.37@6038.3,5038.62
  Bottom Layer w6: v2(5360.58,5529.5) 5360.58,5748.81 5407.95,5796.18 5640.58,5796.18 5664.58,5820.18 5664.58,5924.33 J2.37@5713.71,5973.46
PB5: J1.41 J5.5 U3.91 | length 5103.9
  Top Layer w6: U3.91@6077.67,4428.38 6077.67,4254.28 6047.58,4224.18 6047.58,3989.18 6071.58,3965.18 6832.58,3965.18 6874.58,3923.18 6874.58,3690.39 6934.78,3630.18 7039.58,3630.18 7062.58,3607.18 7062.58,3523.74 J1.41@7113.28,3473.03 ; v2(7331.95,5552.5) 7336.95,5547.5 7336.95,4042.05 v2(7378,4001)
  Bottom Layer w6: J1.41@7113.28,3473.03 7113.28,3417.48 7132.58,3398.18 7555.58,3398.18 7594.95,3437.56 7594.95,3951.05 7554.63,3991.37 7419.63,3991.37 7410,4001 v2(7378,4001) ; J5.5@7113.28,5673.03 7113.28,5612.17 7155.95,5569.5 7314.95,5569.5 v2(7331.95,5552.5)
PB6: JP8.17 U3.92 | length 1595
  Top Layer w6: v2(6072.58,4099.18) 6072.58,4223.18 6099,4249.61 6099,4426.74 U3.92@6097.36,4428.38
  Bottom Layer w6: JP8.17@4990.58,4355.18 4990.58,4312.18 5004.58,4298.18 5117.58,4298.18 5141.58,4274.18 5141.58,4204.24 5195.63,4150.18 6021.58,4150.18 v2(6072.58,4099.18)
PB6_E: J1.42 JP8.18 | length 2752.3
  Top Layer w6: JP8.18@5090.58,4355.18 5128.44,4355.18 5147.91,4335.72 5186.91,4335.72 5187.13,4335.5 ; v2(6113.28,4122.18) 6113.28,4018.48 6154.58,3977.18 6840.58,3977.18 6886.58,3931.18 6886.58,3695.36 6939.75,3642.18 7091.58,3642.18 7113.28,3620.48 J1.42@7113.28,3573.03
  Bottom Layer w6: JP8.18@5090.58,4355.18 5133.58,4355.18 5153.58,4335.18 5153.58,4209.21 5200.61,4162.18 6038.58,4162.18 6078.58,4122.18 v2(6113.28,4122.18) ; J1.42@7113.28,3573.03 J1.42@7113.62,3573.37
PB7: JP8.14 U3.93 | length 1602.1
  Top Layer w6: v2(6094.61,4148.18) 6094.61,4221.21 6117.04,4243.65 U3.93@6117.04,4428.38
  Bottom Layer w6: JP8.14@4990.58,4455.18 5042.58,4403.18 5115.58,4403.18 5165.58,4353.18 5165.58,4214.18 5205.58,4174.18 6068.61,4174.18 v2(6094.61,4148.18)
PB7_E: J1.43 JP8.15 | length 2895.8
  Top Layer w6: v2(6145.58,4135.18) 6145.58,4024.18 6179.58,3990.18 6859.58,3990.18 6898.58,3951.18 6898.58,3700.33 6944.72,3654.18 7143.58,3654.18 7163.58,3634.18 7163.58,3522.74 J1.43@7213.28,3473.03
  Bottom Layer w6: JP8.15@5090.58,4455.18 5102.55,4455.18 5177.58,4380.15 5177.58,4228.18 5219.58,4186.18 6089.63,4186.18 6140.63,4135.18 v2(6145.58,4135.18)
PB8: J1.45 J3.10 R71.2 U3.95 | length 6321.4
  Top Layer w6: v2(5205.95,4474.5) 5205.95,4490.5 5247.95,4532.5 5247.95,4800.5 v2(5388.95,4941.5) ; v2@6156.41,4209.18 U3.95@6156.41,4428.38 ; v2(6156.58,4209.18) 6189.58,4176.18 6189.58,4049.24 6221.63,4017.18 6889.61,4017.18 6922.58,3984.21 6922.58,3710.27 6954.66,3678.18 7238.58,3678.18 7263.58,3653.18 7263.58,3522.74 J1.45@7313.28,3473.03 ; v2(7558,3926) 7525,3959 7525,4090.1 7558.95,4124.06 7558.95,4294.74 7543,4310.7 7543,4417.27 7558.95,4433.22 7558.95,4494.22 v1(7559.23,4494.5) ; v1(7714,4546) 7734,4566 R71.2@7759.34,4566
  Bottom Layer w6: v2(5205.95,4474.5) 5205.95,4246.5 5243.27,4209.18 5289.95,4209.18 6129.58,4209.18 v2(6156.58,4209.18) ; v2(5388.95,4941.5) 5425.95,4978.5 5425.95,5464.47 5458.67,5497.18 5470.95,5497.18 5472.95,5499.18 5720.58,5499.18 5753.28,5531.89 J3.10@5753.28,5673.03 ; J1.45@7313.28,3473.03 7362.58,3522.33 7362.58,3662.18 7385.58,3685.18 7533.58,3685.18 7563.58,3715.18 7563.58,3883.62 7558,3889.2 v2@7558,3924.14 ; 7513.55,3938.12 7544.02,3938.12 ; v1@7557.1,4494.65 7557.25,4494.5 v1(7559.23,4494.5) 7664.95,4494.5 7714,4543.55 v1(7714,4546) ; 7544.02,3938.12 v2@7558,3924.14 ; 7544.02,3938.12 7545.88,3938.12 v2(7558,3926) v2@7558,3924.14
PB9: J1.46 J3.9 U3.96 | length 5290.2
  Top Layer w6: v2(5237.95,4474.5) 5237.95,4491.5 5263.95,4517.5 5263.95,4772.5 v2(5384.95,4893.5) ; U3.96@6176.1,4428.38 6176.1,4264.18 6183.58,4256.7 v2(6183.58,4234.18) 6201.58,4216.18 6201.58,4054.21 6226.61,4029.18 6894.58,4029.18 6934.58,3989.18 6934.58,3715.24 6959.63,3690.18 7286.58,3690.18 7313.28,3663.48 J1.46@7313.28,3573.03
  Bottom Layer w6: v2(5237.95,4474.5) 5237.95,4256.5 5259.45,4235 6182.76,4235 v2(6183.58,4234.18) ; v2(5384.95,4893.5) 5437.95,4946.5 5437.95,5459.5 5463.64,5485.18 5823.58,5485.18 5853.28,5514.89 J3.9@5853.28,5673.03 ; J1.46@7313.28,3573.03 7313.28,3664.89 7345.58,3697.18 7439.58,3697.18 7462.58,3720.18 7462.58,3799.18 7400.58,3861.18 7400.58,3915.42 7376.92,3939.08 7351.46,3939.08
PB10: JP8.8 U3.47 | length 1365.5
  Top Layer w6: JP8.8@4990.58,4655.18 5041.26,4604.5 5188.95,4604.5 5211.95,4627.5 5211.95,4871.5 5362.95,5022.5 5614.95,5022.5 5759.95,5167.5 5821.95,5167.5 5841.45,5148 U3.47@5841.45,5038.62
PB10_E: J2.47 J5.7 JP8.9 R62.1 | length 6618.3
  Top Layer w6: JP8.9@5090.58,4655.18 5170.22,4655.18 5199.95,4684.92 5199.95,4876.47 5357.98,5034.5 5606.95,5034.5 5736.95,5164.5 v2(5736.95,5318.5) 5736.95,5371.5 5648.27,5460.18 5546.58,5460.18 5264.58,5742.18 5264.58,5922.59 J2.47@5213.71,5973.46 ; v2(6908.95,5489.5) 6913.28,5493.82 J5.7@6913.28,5673.03 ; v1@7403.76,4156.78 7403.76,4455.69 7396.14,4463.31 7396.14,4516.5 7403.76,4524.12 7403.76,4852.88 7393.76,4862.88 7393.76,4948.31 7404.95,4959.5 v2(7404.95,5470.5) ; R62.1@8468,4082.34 8468,4027 v1(8469,4026)
  Bottom Layer w6: v2(5736.95,5318.5) 5953.89,5318.5 5971.58,5336.18 5971.58,5449.18 5997.58,5475.18 6894.64,5475.18 v2(6908.95,5489.5) 7179.95,5489.5 7202.32,5467.14 7396.91,5467.14 v2@7397.95,5468.18 ; v1(7405.95,4150.5) 7631.5,4150.5 7692.34,4089.66 7755.7,4089.66 7901.35,3944 8391,3944 8469,4022 v1(8469,4026)
PB11: J7.8 JP8.11 U3.48 | length 3938.8
  Top Layer w6: JP8.11@4990.58,4555.18 5040.26,4505.5 5197.95,4505.5 5235.95,4543.5 5235.95,4827.88 5406.58,4998.5 5623.95,4998.5 5760.27,5134.81 v2(5816.95,5134.81) 5821.76,5130 5821.76,5098.5 U3.48@5821.76,5038.62 ; v2(7139.95,4626.5) 7132,4634.45 7132,5240.43 7139.95,5248.39 v1(7139.95,5273.5)
  Bottom Layer w6: v2(5816.95,5134.81) 6017.89,5134.81 6177.26,5294.18 7029.54,5294.18 7124.27,5294.18 7142.45,5276 v1(7139.95,5273.5) ; v2(7139.95,4626.5) 7575.39,4626.5 J7.8@7628.28,4573.61
PB11_E: J2.48 JP8.12 R75.2 | length 4828.5
  Top Layer w6: JP8.12@5090.58,4555.18 v2(5203.64,4555.18) 5223.95,4575.5 5223.95,4849.77 v2(5359.37,4985.18) ; J2.48@5213.71,5873.46 5213.71,5776.08 5544.61,5445.18 5642.82,5445.18 5710.95,5377.05 5710.95,5155.47 5611.17,5055.69 v2(5395.95,5055.69) ; v1(7633,4307) 7684.54,4358.54 R75.2@7757.51,4358.54
  Bottom Layer w6: v2(5203.64,4555.18) 5398.27,4555.18 5529.95,4423.5 6354.87,4423.5 6416.95,4361.41 6416.95,4261.41 6444.87,4233.5 6964.95,4233.5 7034.45,4303 7629,4303 v1(7633,4307) ; v2(5359.37,4985.18) 5395.95,5021.77 v2(5395.95,5055.69)
PB12: J1.1 J7.7 R74.2 U3.51 | length 5128.2
  Top Layer w6: J1.1@5113.71,3473.46 5058.3,3473.46 5047.58,3484.18 5047.58,3626.53 5085.23,3664.18 5196.64,3664.18 5279.95,3747.5 v2(5279.95,4259.5) 5290.58,4270.12 5290.58,4743.2 5532.56,4985.18 5598.65,4985.18 5614.11,4969.72 U3.51@5713.5,4969.72 ; v2(7481,4088) 7528.28,4135.28 J7.7@7528.28,4573.61 J7.7@7525.39,4576.5 ; v1(7689,4430) 7709,4410 R74.2@7759.34,4410
  Bottom Layer w6: v2(5279.95,4259.5) 5282.45,4257 6224,4257 6243,4238 6243,4148.45 6329.45,4062 7344,4062 7358,4076 7469,4076 v2(7481,4088) ; v2(7527.95,4449.5) 7669.5,4449.5 v1(7689,4430)
PB13: J1.2 J7.3 R73.2 U3.52 | length 5338.8
  Top Layer w6: J1.2@5113.71,3573.46 5113.71,3625.31 5137.58,3649.18 5205.22,3649.18 5302.95,3746.92 5302.95,4738.61 5526.53,4962.18 v2(5539.58,4962.18) 5600.69,4962.18 5610.69,4952.18 5669.33,4952.18 5671.48,4950.03 U3.52@5713.5,4950.03 ; U3.52@5701.5,4952.18 U3.52@5703.65,4950.03 ; 7463.95,5418.5 7463.95,5394.46 7451.95,5382.46 7451.95,5348.5 7463.95,5336.5 7463.95,5178.5 7440.95,5155.5 7440.95,4969.47 7463.95,4946.47 7463.95,4837.94 J7.3@7528.28,4773.61 7578.95,4722.94 7659.52,4722.94 7686.95,4695.5 7686.95,4481.05 7706,4462 R73.2@7759.34,4462
  Bottom Layer w6: v2(5539.58,4962.18) 5539.14,4962.62 5539.14,5240.75 5579.58,5281.18 5961.58,5281.18 5995.58,5315.18 5995.58,5421.18 6021.58,5447.18 7447.21,5447.18 v2(7463.95,5430.44)
PB14: J1.3 J7.1 U3.53 | length 4820.9
  Top Layer w6: J1.3@5213.71,3473.46 5163.58,3523.59 5163.58,3622.12 5178.64,3637.18 5251.63,3637.18 5314.58,3700.12 ; 5314.95,3700.5 5314.95,4733.63 5521.5,4940.18 v2(5573.58,4940.18) 5616.38,4940.18 5626.22,4930.35 U3.53@5713.5,4930.35 ; v2@7480.75,5373.5 7479.54,5374.7 v2(7478.15,5374.7) 7478.15,5174.69 7453.95,5150.5 7453.95,4994.5 7528.28,4920.17 J7.1@7528.28,4873.61
  Bottom Layer w6: v2(5573.58,4940.18) 5573.58,4981.89 5551.14,5004.32 5551.14,5235.75 5584.58,5269.18 5974.58,5269.18 6007.58,5302.18 6007.58,5405.15 6037.61,5435.18 7416.27,5435.18 7478.15,5373.31 v2(7478.15,5374.7)
PB15: J1.4 J7.4 U3.54 | length 4752.4
  Top Layer w6: J1.4@5213.71,3573.46 5213.71,3582.28 5326.58,3695.15 ; 5326.95,3695.53 5326.95,4728.66 5512.79,4914.5 v2(5600.95,4914.5) 5616.74,4914.5 5620.58,4910.66 U3.54@5713.5,4910.66 ; v2@7500.95,5323.5 v2(7500.95,5320.5) 7500.95,5180.5 7465.95,5145.5 7465.95,5021.31 7580.58,4906.69 7580.58,4821.31 J7.4@7628.28,4773.61
  Bottom Layer w6: v2(5600.95,4914.5) 5600.95,4968.97 5602.37,4970.39 5563.14,5009.62 5563.14,5224.75 5595.58,5257.18 5986.58,5257.18 6019.58,5290.18 6019.58,5400.18 6042.58,5423.18 7398.27,5423.18 v2(7500.95,5320.5)
PC0: J2.15 R34.2 U3.15 | length 3747.2
  Top Layer w6: U3.15@6323.73,4772.87 6518.18,4772.87 6596.95,4851.64 v2(6596.95,4878.5) ; v2(6530.58,5085.18) 6530.58,5312.88 6567.58,5349.88 6691.33,5349.88 v2@6744.3,5402.84 ; v2(6744.95,5402.18) 6758.95,5416.18 6758.95,5738.5 6865.58,5845.12 6865.58,5920.74 J2.15@6813.28,5973.03 ; v1(7265.95,5273.5) 7265.95,4034.05 v2(7321,3979)
  Bottom Layer w6: v2(6530.58,5085.18) 6530.58,4995.54 6596.95,4929.17 v2(6596.95,4878.5) ; v2(6744.95,5402.18) 6745.64,5401.5 7163.5,5401.5 7265.95,5299.05 v1(7265.95,5273.5) ; v2(7321,3979) 7324,3976 7365,3976 7404.69,3936.31 R34.2@7455.95,3936.31
PC1: J2.16 R32.2 R77.2 U3.16 | length 4077.9
  Top Layer w6: U3.16@6323.73,4792.55 6501.73,4792.55 6561.95,4852.78 v2(6561.95,4882.5) ; v2(6506.58,5109.18) 6506.58,5315.88 6552.58,5361.88 6667.33,5361.88 v2(6691.95,5386.5) 6739.95,5434.5 6739.95,5785.5 6813.28,5858.83 J2.16@6813.28,5873.03 ; v1(7245,5242) 7245,4387.71 v1(7244.79,4387.5) 7244.95,4012.05 v2(7279,3978) ; v1(7576,4371) 7608,4339 7608,4284 7639,4253 R77.2@7759.34,4253
  Bottom Layer w6: v2(6506.58,5109.18) 6506.58,4986.94 6561.95,4931.56 v2(6561.95,4882.5) ; v2(6691.95,5386.5) 6697.76,5380.69 6914.27,5380.69 6914.95,5381.37 7162.63,5381.37 7244.76,5299.24 7244.76,5242.24 v1(7245,5242) ; v1@7244.76,4388.35 7558.65,4388.35 v1(7576,4371) ; R32.2@7277.78,3937.14 v2@7277.78,3986.5
PC2: J2.17 R72.2 U3.17 | length 3286.6
  Top Layer w6: U3.17@6323.73,4812.24 6498.36,4812.24 6528.95,4842.83 v2(6528.95,4860.5) ; v2(6485.58,5132.18) 6485.58,5320.18 6543.89,5378.5 6644.01,5378.5 6721.95,5456.44 6721.95,5798.43 6764.58,5841.05 6764.58,5921.74 J2.17@6713.28,5973.03 ; v2(7415.95,4915.5) 7415.76,4915.31 7415.76,4500.69 7423.95,4492.5 v1(7416.95,4492.5) ; v1(7717,4505) 7726,4514 R72.2@7759.34,4514
  Bottom Layer w6: v2(6485.58,5132.18) 6485.58,4976.5 6528.95,4933.12 v2(6528.95,4860.5) 6531.76,4857.69 6608.78,4857.69 6669.59,4918.5 7420.95,4918.5 7417.95,4915.5 v2(7415.95,4915.5) ; v1(7416.95,4492.5) 7435.95,4473.5 7436.14,4473.69 7685.69,4473.69 v1(7717,4505)
PC3: J2.18 R67.2 U3.18 | length 3294.5
  Top Layer w6: U3.18@6323.73,4831.92 6487.05,4831.92 v2(6499.14,4844.02) ; v2@6464.76,5153.89 v2(6464.76,5160.61) 6464.76,5180.9 6472,5188.14 6472,5332.71 6539.47,5400.18 6637.95,5400.18 6705.95,5468.18 6705.95,5865.71 J2.18@6713.28,5873.03 ; v1(7288.95,4413.34) 7291,4415.39 v1(7290.95,5143.5)
  Bottom Layer w6: v2(6499.14,4844.02) 6499.14,4931.52 6464.76,4965.89 v2(6464.76,5160.61) 7271.84,5160.61 7289.95,5142.5 v1(7290.95,5143.5) ; v1(7288.95,4413.34) 7289.8,4412.5 7581.24,4412.5 7581.7,4412.96 R67.2@7626.85,4412.96
PC4: J2.33 U3.33 | length 1018.8
  Top Layer w6: J2.33@5913.28,5973.03 5963.58,5922.74 5963.58,5826.18 6009.95,5779.81 6009.95,5600.81 6117.04,5493.72 U3.33@6117.04,5038.62
PC5: J2.34 U3.34 | length 910.7
  Top Layer w6: J2.34@5913.28,5873.03 5913.28,5825.48 5997.95,5740.81 5997.95,5595.84 6097.36,5496.43 U3.34@6097.36,5038.62
PC6: J1.13 U3.63 | length 1700
  Top Layer w6: U3.63@5713.5,4733.5 5484.52,4733.5 5434.95,4683.93 5434.95,4604.5 5472.03,4567.42 5472.03,4014.02 5516.36,3969.69 5545.31,3969.69 5735.58,3779.42 5735.58,3670.7 5665.58,3600.7 5665.58,3521.59 J1.13@5713.71,3473.46
PC7: J1.14 J3.2 U3.64 | length 3469.9
  Top Layer w6: U3.64@5713.5,4713.81 5489.12,4713.81 5446.95,4671.65 5446.95,4609.5 5484.03,4572.42 5484.03,4018.99 5521.33,3981.69 5550.28,3981.69 5751.58,3780.39 5751.58,3650.18 5713.71,3612.31 J1.14@5713.71,3573.46 ; v2(6553.28,5525.89) J3.2@6553.28,5673.03
  Bottom Layer w6: v2(5492.95,4712.5) 5492.95,4907.48 5482.58,4917.86 5482.58,5343.78 5510.98,5372.18 5806.58,5372.18 5945.58,5511.18 6538.58,5511.18 v2(6553.28,5525.89)
PC8: J1.15 R63.2 U3.65 | length 4781.4
  Top Layer w6: U3.65@5713.5,4694.13 5525,4694.13 5517.32,4686.44 5478.72,4686.44 5458.95,4666.68 5458.95,4614.5 5496.03,4577.42 5496.03,4036.42 v2(5529.95,4002.5) 5546.44,4002.5 5763.58,3785.36 5763.58,3523.59 J1.15@5813.71,3473.46 ; v1(7616,4029) v1(7780,4029) ; R63.2@8520,4082.34 8521,4081.34 v1(8521,4026)
  Bottom Layer w6: v2(5529.95,4002.5) 5543.48,3988.98 6863.14,3988.98 6877.12,3975 7103.46,3975 7109.46,3981 7218,3981 7236.81,3999.81 7347.38,3999.81 7382.57,4035 7458,4035 7464,4029 v1(7616,4029) ; v1(7780,4029) 7799.38,4029 7896.38,3932 8427,3932 v1(8521,4026)
PC9: J1.16 U3.66 | length 1496
  Top Layer w6: 5501.57,4674.31 5483.82,4674.31 5483.69,4674.44 ; U3.66@5713.5,4674.44 5483.69,4674.44 ; J1.16@5813.71,3573.46 5813.71,3752.2 5508.03,4057.87 5508.03,4585.71 5470.95,4622.78 5470.95,4661.71 5483.69,4674.44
